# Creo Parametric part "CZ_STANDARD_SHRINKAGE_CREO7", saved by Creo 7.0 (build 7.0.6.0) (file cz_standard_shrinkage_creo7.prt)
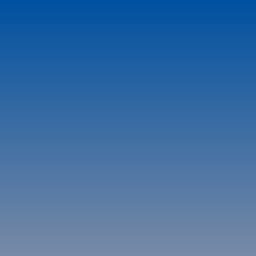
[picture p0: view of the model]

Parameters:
  BEARBEITER = "."
  ERSTELLUNGSDATUM = "."
  KONSTRUKTIONSGRUPPE = "."
  ZEICHNUNGSNUMMER = "000000-0000-000/01"
  TEILDOKUMENT = "001"
  VERSION = "01"
  MATERIALNUMMER = "000000-0000-000"
  KOMP_STUFE = "T"
  KOMP_CHAR = "M"
  BENENNUNG = "XXXXX"

Other parameters: PREIS, Y_SHRINK_FACTOR, Z_SHRINK_FACTOR

Created from: STANDARD_SCHWINDUNG.PRT

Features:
  1. datum plane "Y-Z"
  2. datum plane "X-Z"
  3. datum plane "X-Y"
  4. coordinate system
  5. datum axis
  6. datum axis
  7. datum axis

Other named items: X0Y0Z0, X-ACHSE, Y-ACHSE, Z-ACHSE

Layers: ACHSEN, BOHRUNGSNOTIZEN, EBENEN, FLAECHEN, GEWINDE, KOORDSYS, KURVEN, PUNKTE, RUNDUNGEN, S_ACHSEN, S_EBENEN, S_KOORDSYS, VERBFLAECHE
